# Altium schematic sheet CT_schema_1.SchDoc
size 597 x 258 mm
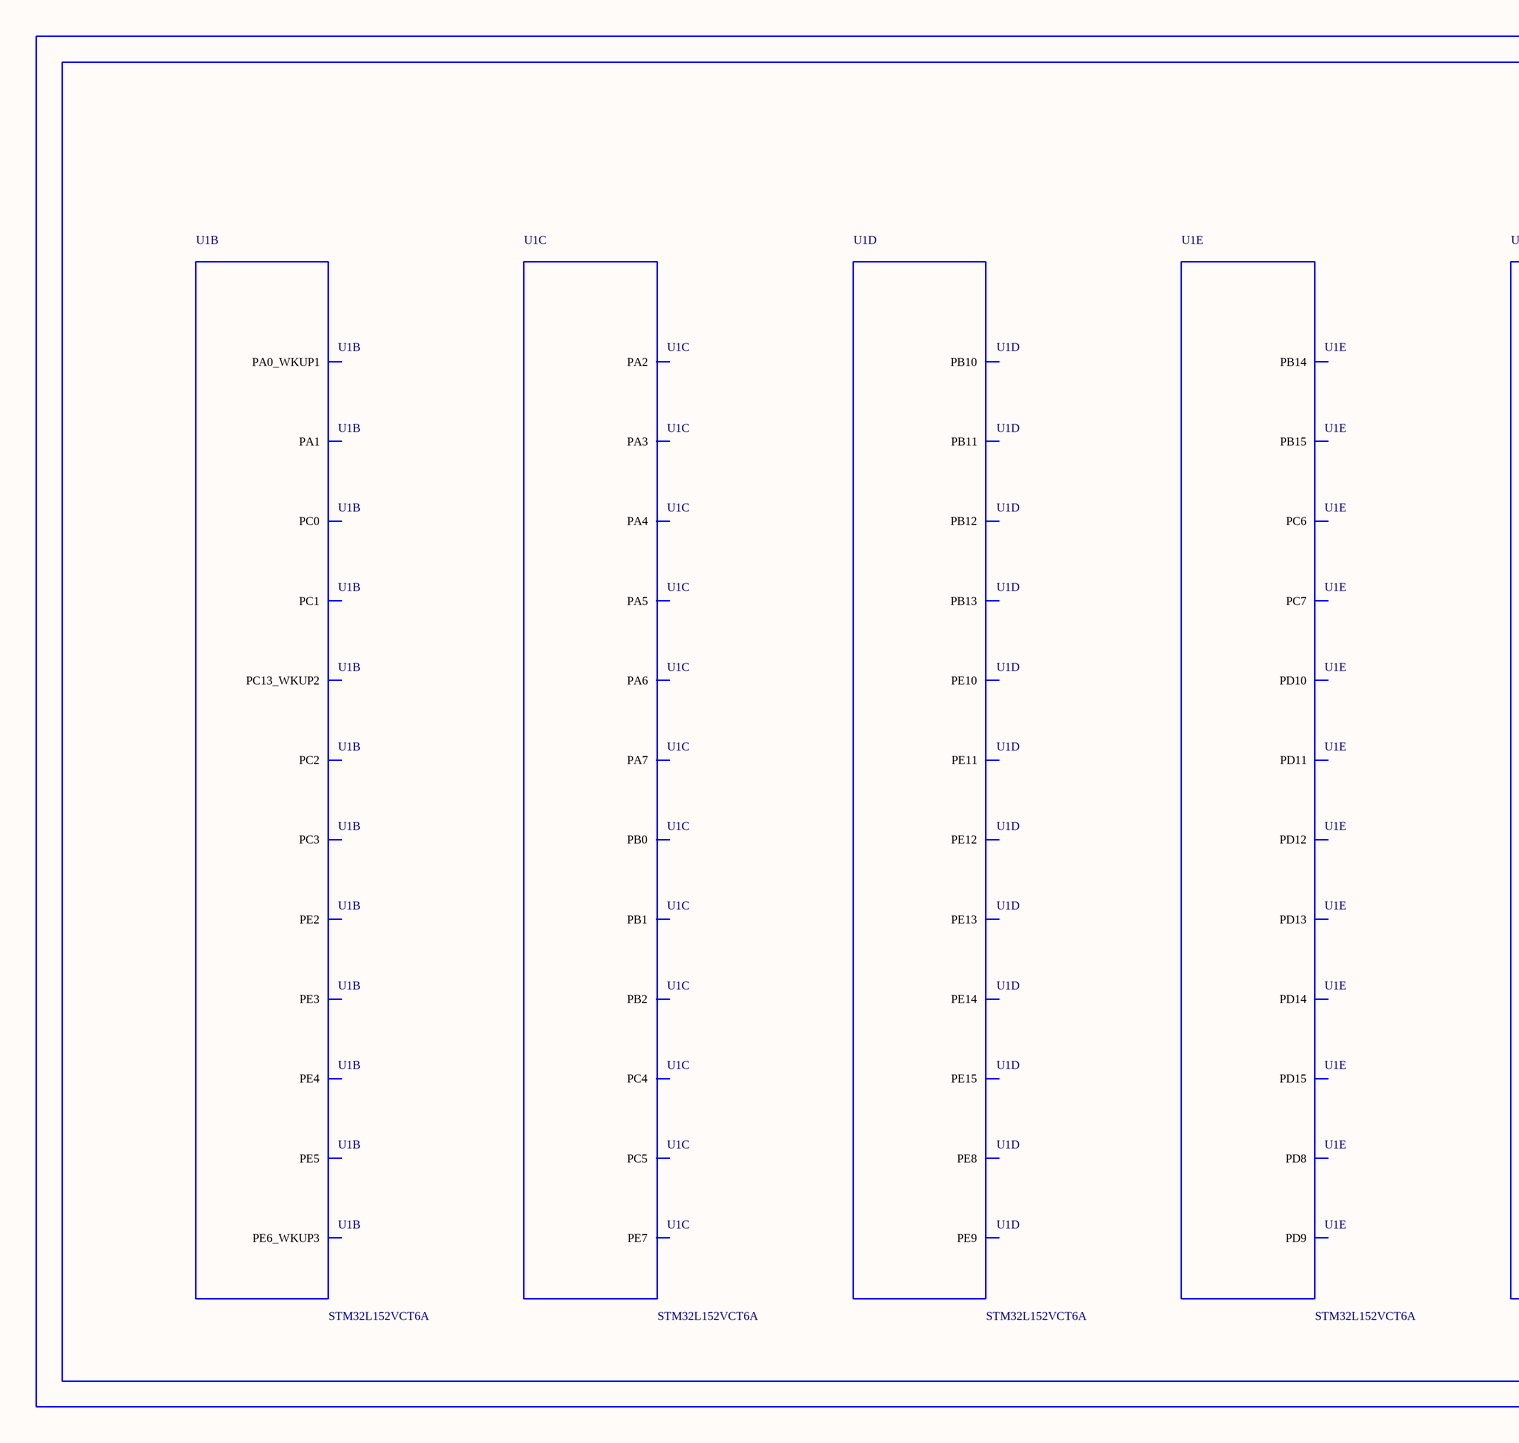
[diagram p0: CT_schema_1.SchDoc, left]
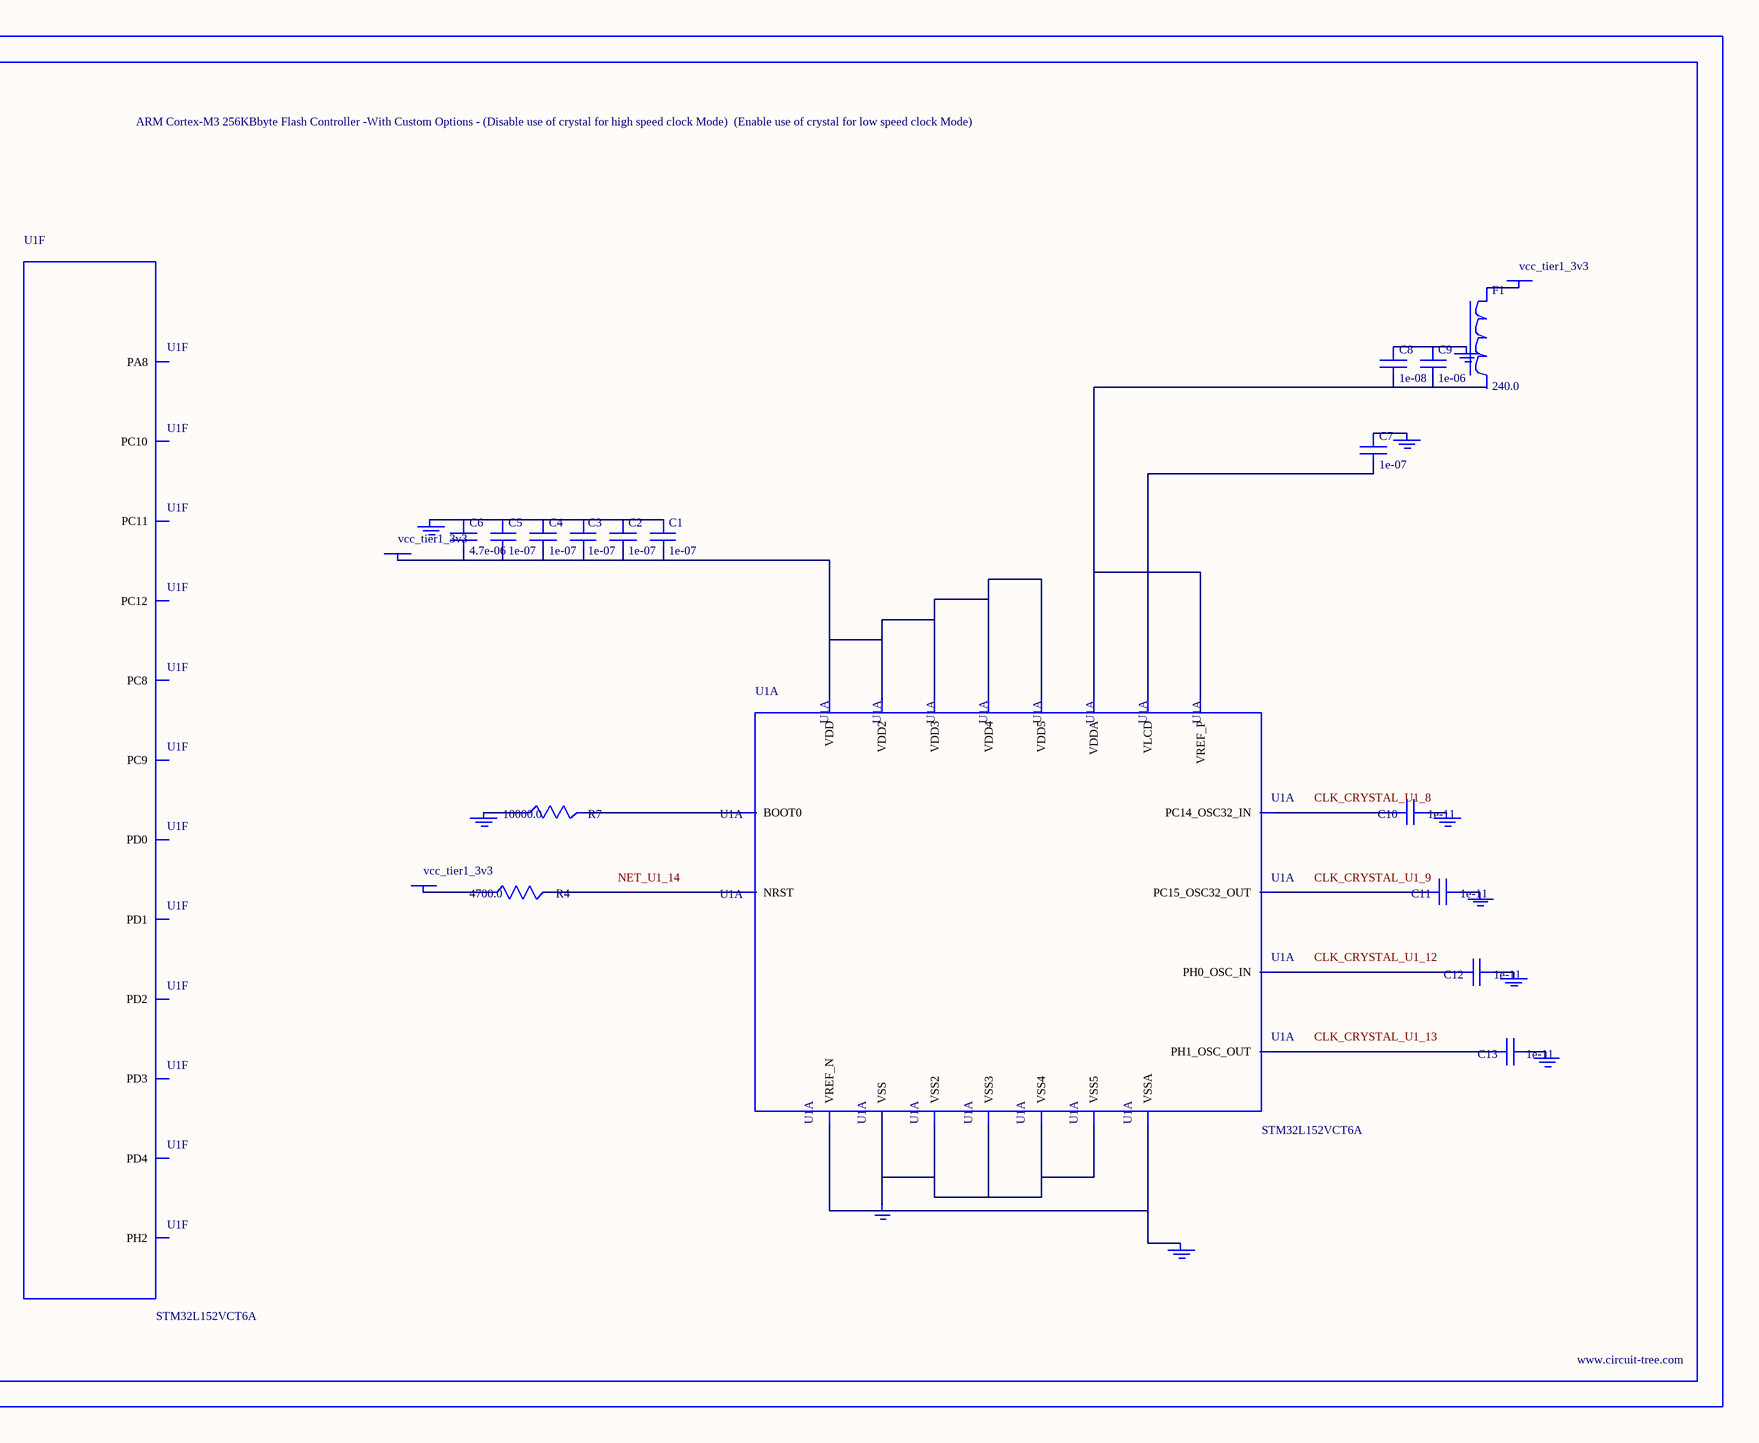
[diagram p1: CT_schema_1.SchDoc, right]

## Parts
BORDER0  (no value)
C1  1e-07  [C0603]
C2  1e-07  [C0603]
C3  1e-07  [C0603]
C4  1e-07  [C0603]
C5  1e-07  [C0603]
C6  4.7e-06  [C0603]
C7  1e-07  [C0603]
C8  1e-08  [C0603]
C9  1e-06  [C0603]
C10  1e-11  [C0402]
C11  1e-11  [C0402]
C12  1e-11  [C0402]
C13  1e-11  [C0402]
F1  240.0  [L0603]
GND_INSTANCE_0_0  (no value)
GND_INSTANCE_0_1  (no value)
GND_INSTANCE_0_2  (no value)
GND_INSTANCE_0_3  (no value)
GND_INSTANCE_0_4  (no value)
GND_INSTANCE_0_5  (no value)
GND_INSTANCE_0_6  (no value)
GND_INSTANCE_0_7  (no value)
GND_INSTANCE_0_8  (no value)
GND_INSTANCE_0_9  (no value)
POWER_INSTANCE_0_0  vcc_tier1_3v3
POWER_INSTANCE_0_1  vcc_tier1_3v3
POWER_INSTANCE_0_2  vcc_tier1_3v3
R4  4700.0  [R0603]
R7  10000.0  [R0603]
U1  STM32L152VCT6A  [LQFP100]  (parts A,B,C,D,E,F of 9)

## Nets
NetC1_1: C1.1 C2.1 C3.1 C4.1 C5.1 C6.1 GND_INSTANCE_0_3.0(GND)
NetC1_2: C1.2 C2.2 C3.2 C4.2 C5.2 C6.2 POWER_INSTANCE_0_0.0(PWR) U1.11(VDD) U1.28(VDD2) U1.50(VDD3) U1.75(VDD4) U1.100(VDD5)
NetC7_1: C7.1 GND_INSTANCE_0_0.0(GND)
NetC7_2: C7.2 U1.6(VLCD)
NetC8_1: C8.1 C9.1 GND_INSTANCE_0_7.0(GND)
NetC8_2: C8.2 C9.2 U1.21(VREF_P) U1.22(VDDA)
NetC10_1: C10.1 GND_INSTANCE_0_1.0(GND)
NetC10_2: C10.2 U1.8(PC14_OSC32_IN)
NetC11_1: C11.1 GND_INSTANCE_0_2.0(GND)
NetC11_2: C11.2 U1.9(PC15_OSC32_OUT)
NetC12_1: C12.1 GND_INSTANCE_0_4.0(GND)
NetC12_2: C12.2 U1.12(PH0_OSC_IN)
NetC13_1: C13.1 GND_INSTANCE_0_5.0(GND)
NetC13_2: C13.2 U1.13(PH1_OSC_OUT)
NetF1_1: F1.1 POWER_INSTANCE_0_1.0(PWR)
NetGND_INSTANCE_0_6_0: GND_INSTANCE_0_6.0(GND) U1.19(VSSA) U1.20(VREF_N)
NetGND_INSTANCE_0_8_0: GND_INSTANCE_0_8.0(GND) R7.1
NetGND_INSTANCE_0_9_0: GND_INSTANCE_0_9.0(GND) U1.10(VSS) U1.27(VSS2) U1.49(VSS3) U1.74(VSS4) U1.99(VSS5)
NetPOWER_INSTANCE_0_2_0: POWER_INSTANCE_0_2.0(PWR) R4.1
NetR4_2: R4.2 U1.14(NRST)
NetR7_2: R7.2 U1.94(BOOT0)

Not connected (* = marked no-connect by the designer): F1 2; U1 1(PE2) 2(PE3) 3(PE4) 4(PE5) 5(PE6_WKUP3) 7(PC13_WKUP2) 15(PC0) 16(PC1) 17(PC2) 18(PC3) 23(PA0_WKUP1) 24(PA1) 25(PA2) 26(PA3) 29(PA4) 30(PA5) 31(PA6) 32(PA7) 33(PC4) 34(PC5) 35(PB0) 36(PB1) 37(PB2) 38(PE7) 39(PE8) 40(PE9) 41(PE10) 42(PE11) 43(PE12) 44(PE13) 45(PE14) 46(PE15) 47(PB10) 48(PB11) 51(PB12) 52(PB13) 53(PB14) 54(PB15) 55(PD8) 56(PD9) 57(PD10) 58(PD11) 59(PD12) 60(PD13) 61(PD14) 62(PD15) 63(PC6) 64(PC7) 65(PC8) 66(PC9) 67(PA8) 73(PH2) 78(PC10) 79(PC11) 80(PC12) 81(PD0) 82(PD1) 83(PD2) 84(PD3) 85(PD4)

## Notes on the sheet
- Labels drawn without touching a wire or pin: CLK_CRYSTAL_U1_8, CLK_CRYSTAL_U1_9, CLK_CRYSTAL_U1_12, CLK_CRYSTAL_U1_13, NET_U1_14

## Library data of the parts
BORDER0 = BORDER_PAGE0
C1-C5 C7 = 06035C104K4Z2A
C6 = GRM188R6YA475KE15D
C8 = 06035C103K4Z2A
C9 = C0603C105K3RACTU
C10-C13 = C0402C100K3GACTU
F1 = Z0603C241ASMST
GND_INSTANCE_0_0-GND_INSTANCE_0_9 = GND
POWER_INSTANCE_0_0-POWER_INSTANCE_0_2 = PWR
R4 = RC0603JR-074K7L
R7 = RC0603JR-0710KL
